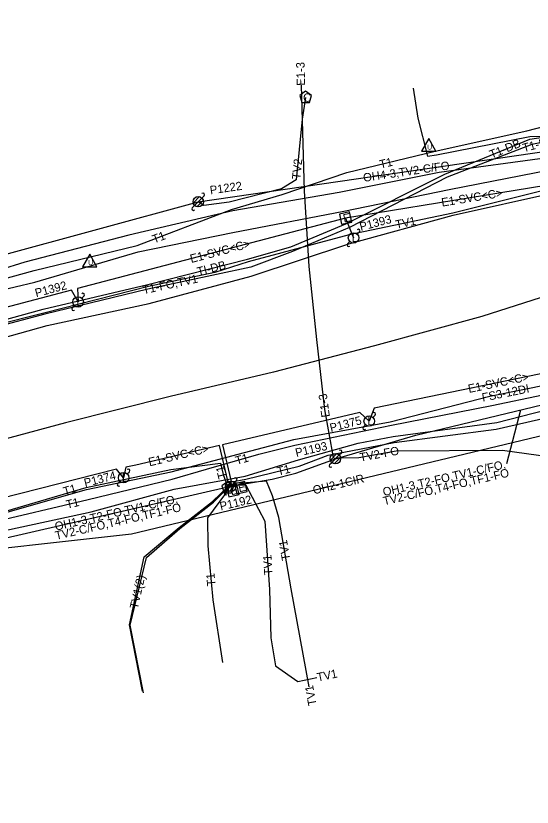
# Model space of a CAD drawing. Extents: x 2336688 to 2352634, y 362473 to 369571.
# Drawn here: x 2351485 to 2351731.6, y 368636.2 to 369013.7 of the extents above; entities that cross this region are included whole.
import ezdxf

# ---------------------------------------------------------------- set-up
doc = ezdxf.new("R2010")
doc.units = 0
for name, color, linetype in [('RD_EX_DV_Prop', 7, 'Continuous'), ('RD_EX_DV_TX_Prop', 7, 'Continuous'), ('RD_EX_RW', 7, 'Continuous'), ('RD_EX_RW_TX', 7, 'Continuous'), ('RD_HC_CL_Rel', 7, 'Continuous'), ('RD_HC_Data_Tic', 7, 'Continuous'), ('RD_PD_Final_TrvlWay', 7, 'Continuous'), ('RD_PD_PatLn3', 7, 'Continuous'), ('RD_PD_PatLn4', 7, 'Continuous'), ('RD_SHT_ShtClip', 7, 'Continuous'), ('RD_Sketch1', 7, 'Continuous'), ('RD_Sketch2', 7, 'Continuous'), ('RD_Sketch5', 7, 'Continuous')]:
    doc.layers.add(name, color=color, linetype=linetype)

msp = doc.modelspace()

# ---------------------------------------------------------------- linework, layer by layer
at = {"layer": 'RD_EX_RW_TX'}
for points in [[(2351674.66, 368979.28), (2351676.95, 368964.93), (2351681.61, 368946.8), (2351685.81, 368947.48), (2351730.37, 368956.23), (2351762.74, 368956.69), (2351770.03, 368960.75), (2351774.28, 368967.37), (2351800.15, 368972.4), (2351872.17, 368980.36), (2351937.74, 368982.19), (2351987.22, 368989.17), (2352041.91, 368999.4), (2352065.6, 369002.37), (2352089.73, 369004.61), (2352102.55, 369007.6), (2352102.58, 369015.62), (2352100.79, 369043.46)], [(2351441.13, 368877.68), (2351493.72, 368892.16), (2351542.92, 368904.09), (2351587.97, 368921.36), (2351612.24, 368928.51), (2351643.03, 368939.04), (2351685.22, 368949.09), (2351729.04, 368958.84), (2351768.34, 368969.01), (2351799.1, 368976.84), (2351807.9, 368981.96), (2351811.24, 368986.71), (2351812.17, 368997.01)], [(2351776.48, 368993.53), (2351781.05, 368981.28), (2351776.85, 368959.84), (2351775.71, 368957.81), (2351774.05, 368953.89), (2351770.61, 368943.72), (2351762.16, 368935.08), (2351741.35, 368931.51), (2351693.7, 368919.57), (2351644.17, 368909.19), (2351595.95, 368896.32), (2351580.02, 368891.2), (2351548.35, 368884.52), (2351499.06, 368872), (2351450.2, 368859.78)], [(2351623.41, 368974.73), (2351621.68, 368964.43), (2351618.81, 368935.45), (2351611.88, 368931.12), (2351586.91, 368924.82), (2351574.75, 368923.22), (2351572.13, 368925.03)], [(2351450, 368860.64), (2351498.06, 368873.82), (2351548.09, 368885.57), (2351595.68, 368897.58), (2351616.34, 368903.53), (2351642.63, 368914.43), (2351689.81, 368938.15), (2351730.46, 368954.84), (2351762.28, 368959.7), (2351765.09, 368961.33), (2351764.64, 368959.22), (2351767.74, 368939.28), (2351792.58, 368943.98), (2351835.36, 368954.52), (2351880.81, 368963.77), (2351939.3, 368973.2)], [(2351026.67, 368705.73), (2351072.69, 368726.31), (2351095.34, 368740.06), (2351116.22, 368749.97), (2351165.51, 368767.17), (2351212.21, 368781.21), (2351311.35, 368807.4), (2351356.55, 368822.99), (2351403.13, 368840.09), (2351451.54, 368852.43), (2351499.93, 368866.02), (2351548.68, 368876.43), (2351597.38, 368889.51), (2351644.05, 368904.92), (2351693.91, 368918.56), (2351742.3, 368929.46), (2351791.99, 368937.8), (2351833.59, 368947.12), (2351885, 368956.88), (2351939.56, 368969.89)], [(2351765.09, 368961.33), (2351762.65, 368958.7), (2351731.46, 368952.33), (2351690.92, 368936.8), (2351644.39, 368912.81), (2351617.15, 368901.31), (2351597.28, 368893.86), (2351548.04, 368883.26), (2351498.82, 368871.39), (2351450.63, 368858.65), (2351402.34, 368844.85), (2351353.62, 368832.17), (2351306.23, 368821.59), (2351280.49, 368815.25), (2351211.24, 368794.97), (2351186.06, 368787.7), (2351186.43, 368794.28), (2351186.89, 368796.09), (2351185.08, 368794.48), (2351153.67, 368786.02), (2351107.67, 368770.53), (2351057.77, 368748.3), (2351012.48, 368735.27)], [(2351356.36, 368718.44), (2351351.37, 368734.97), (2351351.07, 368736.27), (2351352.08, 368735.83), (2351354.55, 368734.64), (2351363.44, 368738.12), (2351379.73, 368744.54), (2351398.33, 368751.76), (2351424.73, 368759.16), (2351470.85, 368771.57), (2351519.59, 368782.94), (2351559.62, 368792.7), (2351576.11, 368797.45), (2351601.1, 368804.55), (2351618.26, 368808.83), (2351664.35, 368818.5), (2351712.26, 368827.78), (2351760.99, 368838.04), (2351806.87, 368848.05), (2351854.2, 368855.12), (2351907.65, 368859.27)], [(2351469.79, 368774.45), (2351518.56, 368788.63), (2351559.06, 368797.29), (2351582.72, 368800.31), (2351584.07, 368794.92), (2351586.12, 368789.37), (2351586.25, 368788.52), (2351587.94, 368791.42), (2351594.9, 368792.63), (2351620.36, 368798.87), (2351634.16, 368804.06), (2351665.64, 368810.12), (2351714.33, 368816.59), (2351756.9, 368826.27), (2351758.66, 368825.96), (2351758.35, 368824.95), (2351762.12, 368809.74), (2351767.08, 368791.96), (2351783.55, 368756.14), (2351799.72, 368708.59)], [(2351637.62, 368802.44), (2351638.61, 368802.8), (2351648.75, 368802.95), (2351666.69, 368806.19), (2351717.35, 368806.44), (2351770.06, 368799.18), (2351777.6, 368793.92), (2351790.36, 368754.99), (2351783.74, 368729.96), (2351788.08, 368706.76)], [(2351625.07, 368693.54), (2351616.41, 368740.37), (2351610.63, 368774.42), (2351607.5, 368784.76), (2351604.72, 368791.7), (2351595.18, 368790.94), (2351589.52, 368790.79), (2351587.61, 368789.27)], [(2351587.61, 368789.27), (2351589.38, 368790.08), (2351594.9, 368789.88), (2351603.97, 368772.62), (2351606.11, 368740.04), (2351606.84, 368717.03), (2351608.99, 368703.6), (2351619.73, 368696.22), (2351628.76, 368698.08)], [(2351545.53, 368691.54), (2351539.37, 368723.16), (2351546.28, 368755.58), (2351562.96, 368769.66), (2351578.99, 368782.09), (2351586.82, 368789.69), (2351587.61, 368789.27)], [(2351545.91, 368690.72), (2351539.63, 368723), (2351547.42, 368755.32), (2351563.31, 368769.17), (2351579.4, 368781.64), (2351586.79, 368789.03), (2351587.61, 368789.27)], [(2351586.25, 368788.52), (2351585.15, 368785.85), (2351576.62, 368774.28), (2351576.63, 368760.87), (2351579.03, 368735.04), (2351583.67, 368705.25)]]:
    msp.add_lwpolyline(points, dxfattribs=at)
for points in [[(2351623.41, 368977.73), (2351620.56, 368975.65), (2351621.65, 368972.3), (2351625.17, 368972.3), (2351626.26, 368975.65)], [(2351586.25, 368791.52), (2351583.4, 368789.45), (2351584.49, 368786.09), (2351588.01, 368786.09), (2351589.1, 368789.45)]]:
    msp.add_lwpolyline(points, close=True, dxfattribs=at)
at = {"layer": 'RD_HC_CL_Rel'}
for points in [[(2351211.87, 369060.2), (2351223.48, 369007.05), (2351235.68, 368951.97), (2351248.3, 368899.28), (2351256.86, 368864.38), (2351258.4, 368860.79), (2351267.06, 368853.06), (2351279.19, 368842.1), (2351287.59, 368836.67), (2351300.9, 368835.62), (2351301.79, 368834.14), (2351303.04, 368833.64), (2351320.88, 368837.27), (2351336.77, 368841.59), (2351351.45, 368846.05), (2351396.57, 368859.65), (2351447.03, 368875.53), (2351494.07, 368886.58), (2351543.46, 368901.18), (2351588.65, 368910.33), (2351641.69, 368920.56), (2351691.88, 368930.79), (2351740.06, 368940.33), (2351801.74, 368956.51)], [(2351470.14, 368766.16), (2351521.03, 368777.02), (2351560.63, 368787.9), (2351594.48, 368794.14), (2351619.97, 368801.96), (2351648.53, 368809.83), (2351665.14, 368813.04), (2351714.69, 368819.75), (2351761.78, 368831.73), (2351809.21, 368838.57), (2351856.12, 368845.07), (2351908.31, 368852.47)]]:
    msp.add_lwpolyline(points, dxfattribs=at)
at = {"layer": 'RD_HC_Data_Tic'}
for p, q in [((2351569.71, 368924.38), (2351572.77, 368927.45)), ((2351570.36, 368923.26), (2351573.89, 368926.8)), ((2351571.48, 368922.62), (2351574.54, 368925.68)), ((2351573.89, 368926.8), (2351574.96, 368927.86)), ((2351569.3, 368922.2), (2351570.36, 368923.26)), ((2351648.03, 368909.53), (2351649.1, 368910.6)), ((2351643.44, 368904.94), (2351644.5, 368906)), ((2351516.54, 368878.99), (2351517.6, 368880.06)), ((2351511.94, 368874.4), (2351513, 368875.46)), ((2351655.5, 368822.15), (2351656.56, 368823.21)), ((2351650.91, 368817.56), (2351651.97, 368818.62)), ((2351635.2, 368801.79), (2351638.27, 368804.86)), ((2351639.39, 368804.21), (2351640.45, 368805.27)), ((2351635.85, 368800.67), (2351639.39, 368804.21)), ((2351636.97, 368800.03), (2351640.03, 368803.09)), ((2351634.79, 368799.61), (2351635.85, 368800.67)), ((2351538.26, 368795.15), (2351539.32, 368796.21)), ((2351533.66, 368790.55), (2351534.72, 368791.61)), ((2351585.19, 368788.62), (2351588.25, 368791.69)), ((2351585.84, 368787.5), (2351589.37, 368791.04)), ((2351586.96, 368786.86), (2351590.02, 368789.92)), ((2351589.37, 368791.04), (2351590.43, 368792.1)), ((2351584.78, 368786.44), (2351585.84, 368787.5))]:
    msp.add_line(p, q, dxfattribs=at)
for centre in [(2351572.13, 368925.03), (2351646.27, 368907.77), (2351514.77, 368877.23), (2351653.74, 368820.38), (2351637.62, 368802.44), (2351536.49, 368793.38), (2351587.61, 368789.27)]:
    msp.add_circle(centre, 2.5, dxfattribs=at)
for centre, start, end in [((2351574.43, 368928.39), 315, 135), ((2351569.83, 368921.67), 135, 315), ((2351648.57, 368911.13), 315, 135), ((2351643.97, 368904.41), 135, 315), ((2351517.07, 368880.59), 315, 135), ((2351512.47, 368873.87), 135, 315), ((2351656.03, 368823.74), 315, 135), ((2351651.44, 368817.03), 135, 315), ((2351639.92, 368805.8), 315, 135), ((2351538.79, 368796.74), 315, 135), ((2351635.32, 368799.08), 135, 315), ((2351534.19, 368790.02), 135, 315), ((2351589.9, 368792.63), 315, 135), ((2351585.31, 368785.91), 135, 315)]:
    msp.add_arc(centre, 0.75, start, end, dxfattribs=at)
at = {"layer": 'RD_PD_Final_TrvlWay'}
msp.add_line((2351642.49, 368917.24), (2351646.27, 368907.77), dxfattribs=at)
for points in [[(2351813.53, 369029.36), (2351821.49, 368992.14), (2351823.9, 368989.67), (2351794.62, 368950.67), (2351778.05, 368940.44), (2351775.15, 368938.78), (2351642.49, 368917.24), (2351514.5, 368883.56), (2351514.77, 368877.23), (2351511.62, 368882.8), (2351407.12, 368855.31), (2351405.59, 368848.58), (2351402.3, 368851.72), (2351332.34, 368833.32), (2351331.07, 368827.87)], [(2351621.26, 368980.68), (2351622.74, 368930.2), (2351625, 368894.07), (2351628.51, 368859.31), (2351632.34, 368825.87), (2351636.57, 368802.98), (2351637.62, 368802.44)], [(2351962.19, 368868.54), (2351879.61, 368860.3), (2351872.73, 368864.24), (2351807.16, 368856.02), (2351766.5, 368848.48), (2351760.54, 368842.85), (2351755.71, 368847.01), (2351656.05, 368826.47), (2351653.74, 368820.38), (2351649.2, 368824.53), (2351583.65, 368809.05), (2351587.65, 368792.13), (2351587.61, 368789.27), (2351586.29, 368791.8), (2351582.29, 368808.73), (2351542.35, 368799.3), (2351537.51, 368798.37), (2351536.49, 368793.38), (2351533.02, 368797.4), (2351459.1, 368778.67), (2351456.43, 368773.13), (2351451.34, 368775.83), (2351353, 368749.17), (2351345.06, 368741.32)]]:
    msp.add_lwpolyline(points, dxfattribs=at)
for points in [[(2351644.41, 368920.21), (2351639.52, 368919.16), (2351640.57, 368914.27), (2351645.46, 368915.32)], [(2351590.56, 368790.18), (2351585.68, 368789.07), (2351586.79, 368784.2), (2351591.67, 368785.31)], [(2351594.3, 368791.6), (2351589.42, 368790.49), (2351590.53, 368785.61), (2351595.41, 368786.72)]]:
    msp.add_lwpolyline(points, close=True, dxfattribs=at)
at = {"layer": 'RD_PD_PatLn3'}
for points in [[(2351682.14, 368955.13), (2351678.68, 368949.13), (2351685.61, 368949.13)], [(2351520.32, 368900.03), (2351516.85, 368894.03), (2351523.78, 368894.03)]]:
    msp.add_lwpolyline(points, close=True, dxfattribs=at)
at = {"layer": 'RD_PD_PatLn4'}
msp.add_line((2351719.52, 368800.09), (2351726.12, 368825.7), dxfattribs=at)
at = {"layer": 'RD_SHT_ShtClip'}
for p, q in [((2351572.13, 368925.03), (2351827.12, 368962.06)), ((2351197.21, 368822.78), (2351572.13, 368925.03)), ((2351439.98, 368755.4), (2351587.61, 368789.27))]:
    msp.add_line(p, q, dxfattribs=at)
for points in [[(2351439.98, 368755.4), (2351540.29, 368766.59), (2351738.13, 368814.04), (2351832.35, 368849.22)], [(2351637.62, 368802.44), (2351676.06, 368813.68), (2351793, 368841.77), (2351832.35, 368849.22)], [(2351587.61, 368789.27), (2351607.4, 368792.62), (2351618.74, 368795.61), (2351637.62, 368802.44)]]:
    msp.add_lwpolyline(points, dxfattribs=at)
at = {"layer": 'RD_Sketch2'}
for points in [[(2351829.3, 368956.12), (2351825.48, 368955.65), (2351796.45, 368952.27), (2351741.12, 368946.36), (2351687.12, 368939), (2351639.33, 368929.45), (2351588.67, 368920.67), (2351539, 368909.06), (2351489.27, 368896.27), (2351440.12, 368880.97), (2351434.75, 368879.34), (2351397.29, 368866.24), (2351394.12, 368865.24), (2351393.38, 368867.94), (2351392.71, 368869.71)], [(2351897.87, 368918.99), (2351839.37, 368906.5), (2351797.47, 368896.96), (2351751.8, 368884.48), (2351707.52, 368870.2), (2351656.24, 368856.32), (2351608.11, 368843.77), (2351558.65, 368832.09), (2351508.67, 368819.53), (2351459.49, 368806.33), (2351412.81, 368793.12), (2351368.32, 368777.82), (2351320.48, 368761.6), (2351291.49, 368752.07), (2351283.21, 368749.13), (2351230.34, 368719.64), (2351184.82, 368699.7), (2351136.28, 368683.67), (2351113.69, 368676.51), (2351093.58, 368668.35), (2351042.86, 368655.18), (2350995.25, 368636.19)]]:
    msp.add_lwpolyline(points, dxfattribs=at)
at = {"layer": 'RD_Sketch5'}
msp.add_lwpolyline([(2351470.05, 368773.88), (2351518.77, 368787.72), (2351559.13, 368796.23), (2351617.79, 368811.57), (2351663.83, 368820.09), (2351711.27, 368832.32), (2351740.53, 368838.18), (2351747.1, 368846.93), (2351757.38, 368857), (2351803.33, 368866.61), (2351852.53, 368877.54), (2351904.23, 368891.75)], dxfattribs=at)

# ---------------------------------------------------------------- texts
at = {"layer": 'RD_EX_DV_Prop'}
for s, rotation, p in [('E1-3', 91.6745, (2351623.17, 368980.43)), ('E1-SVC<C>', 9.2228, (2351688.54, 368922.69)), ('E1-SVC<C>', 14.7421, (2351568.8, 368895.78)), ('E1-SVC<C>', 11.6478, (2351701.4, 368833.78)), ('E1-3', 97.8001, (2351634.99, 368822.45)), ('E1-SVC<C>', 13.2845, (2351548.85, 368798.78))]:
    msp.add_text(s, height=4, rotation=rotation, dxfattribs=at).set_placement(p)
at = {"layer": 'RD_EX_DV_TX_Prop'}
for s, rotation, p in [('P1222', 8.2617, (2351577.96, 368928.53)), ('P1393', 14.7421, (2351649.75, 368911.07)), ('P1392', 14.7421, (2351494.76, 368879.47)), ('P1375', 14.3887, (2351635.47, 368815.13)), ('P1193', 12.9211, (2351618.96, 368803.26)), ('P1374', 14.3887, (2351518.16, 368788.85)), ('P1192', 12.9211, (2351582.89, 368777.71))]:
    msp.add_text(s, height=4, rotation=rotation, dxfattribs=at).set_placement(p)
at = {"layer": 'RD_EX_RW'}
for s, rotation, p in [('T1-FO', 14.5402, (2351727.53, 368948.67)), ('T1-DB', 22.3164, (2351712.17, 368945.53)), ('TV2', 84.3337, (2351620.83, 368935.58)), ('T1', 13.3865, (2351659.16, 368940.83)), ('TV1', 11.8322, (2351666.74, 368912.11)), ('T1', 20.9773, (2351551.07, 368905.07)), ('TI-DB', 14.173, (2351572.12, 368889.66)), ('T1-FO,TV1', 12.1573, (2351546.05, 368880.9)), ('TV2-FO', 10.2298, (2351649.56, 368801.06)), ('T1', 15.8615, (2351590.48, 368799.46)), ('T1', 104.0312, (2351585.77, 368793.41)), ('T1', 13.7733, (2351610.36, 368794.36)), ('T1', 16.2143, (2351508.34, 368784.81)), ('T1', 13.1339, (2351509.53, 368778.54)), ('TV1', 99.6475, (2351616.09, 368754.23)), ('TV1', 93.7559, (2351607.66, 368747)), ('TV1(2)', 77.1702, (2351543.23, 368730.54)), ('T1', 95.3132, (2351580.41, 368741.84)), ('TV1', 11.6329, (2351629.19, 368696.12)), ('TV1', 100.4742, (2351628.68, 368685))]:
    msp.add_text(s, height=4, rotation=rotation, dxfattribs=at).set_placement(p)
at = {"layer": 'RD_EX_RW_TX'}
for s, height, p in [('C', 4, (2351622.18, 368972.73)), ('T', 3.75, (2351585.02, 368786.29))]:
    msp.add_text(s, height=height, dxfattribs=at).set_placement(p)
at = {"layer": 'RD_HC_Data_Tic'}
for p in [(2351645.46, 368905.83), (2351513.96, 368875.29), (2351652.92, 368818.45), (2351535.68, 368791.45)]:
    msp.add_text('L', height=4, rotation=360, dxfattribs=at).set_placement(p)
at = {"layer": 'RD_PD_Final_TrvlWay'}
for rotation, p in [(12.1277, (2351641.72, 368915.03)), (12.8362, (2351591.68, 368786.39)), (12.8362, (2351587.94, 368784.97))]:
    msp.add_text('E', height=4, rotation=rotation, dxfattribs=at).set_placement(p)
at = {"layer": 'RD_PD_PatLn3'}
for p in [(2351681.39, 368949.93), (2351519.56, 368894.83)]:
    msp.add_text('U', height=2.4, dxfattribs=at).set_placement(p)
at = {"layer": 'RD_PD_PatLn4'}
for s, rotation, p in [('OH4-3,TV2-C/FO', 8.2617, (2351651.15, 368934.48)), ('OH1-3,T2-FO,TV1-C/FO,', 12.9211, (2351660.73, 368784.55)), ('TV2-C/FO,T4-FO,TF1-FO', 12.9211, (2351660.88, 368780.2)), ('OH2-1CIR', 13.4871, (2351627.37, 368785.42)), ('OH1-3,T2-FO,TV1-C/FO,', 12.9211, (2351504.16, 368768.08)), ('TV2-C/FO,T4-FO,TF1-FO', 12.9211, (2351504.32, 368763.72))]:
    msp.add_text(s, height=4, rotation=rotation, dxfattribs=at).set_placement(p)
at = {"layer": 'RD_Sketch1'}
msp.add_text('FS3-12DI', height=4, rotation=11.3303, dxfattribs=at).set_placement((2351707.98, 368829.61))

doc.saveas('drawing.dxf')
